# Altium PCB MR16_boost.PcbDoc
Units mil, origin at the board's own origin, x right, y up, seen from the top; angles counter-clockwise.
Board outline 800 x 860 mil, 2 copper layers (Top Layer, Bottom Layer), stack 62 mil thick; 24 components, 14 nets, 60 pads, 8 vias.
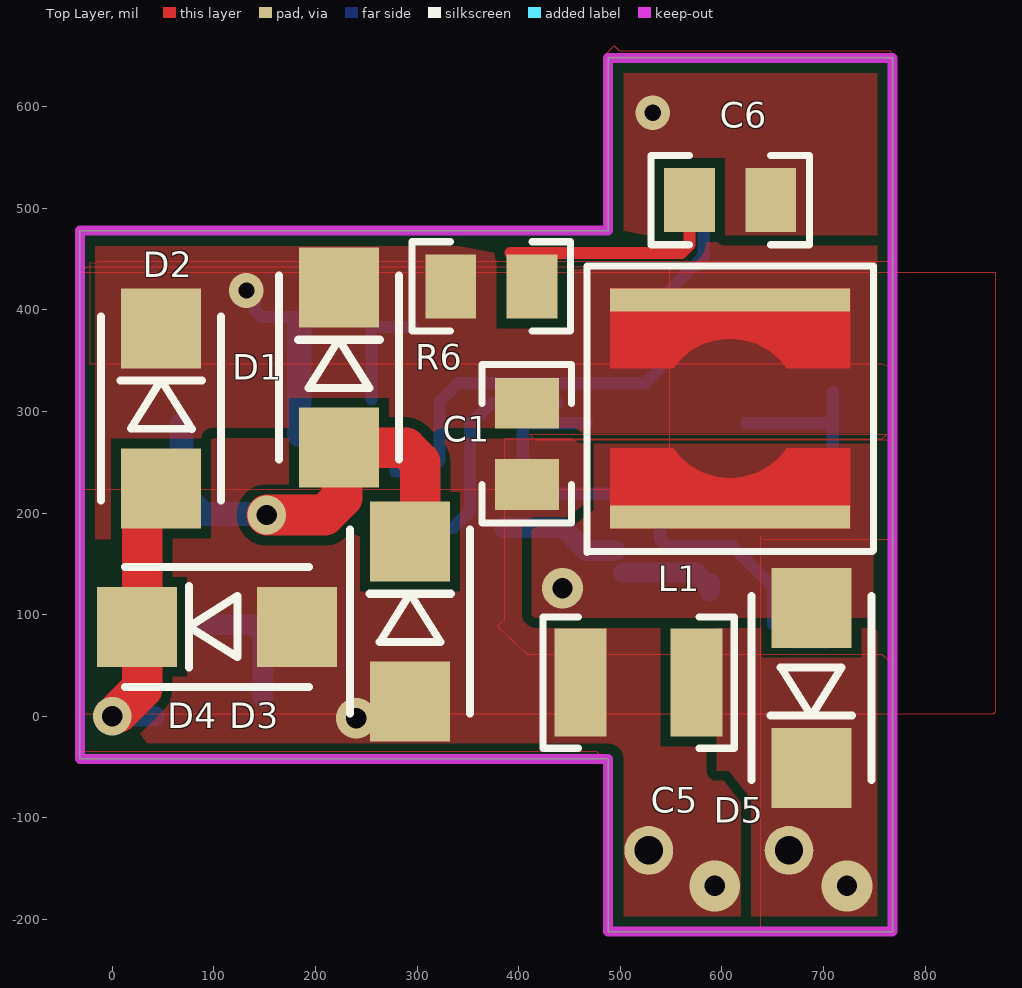
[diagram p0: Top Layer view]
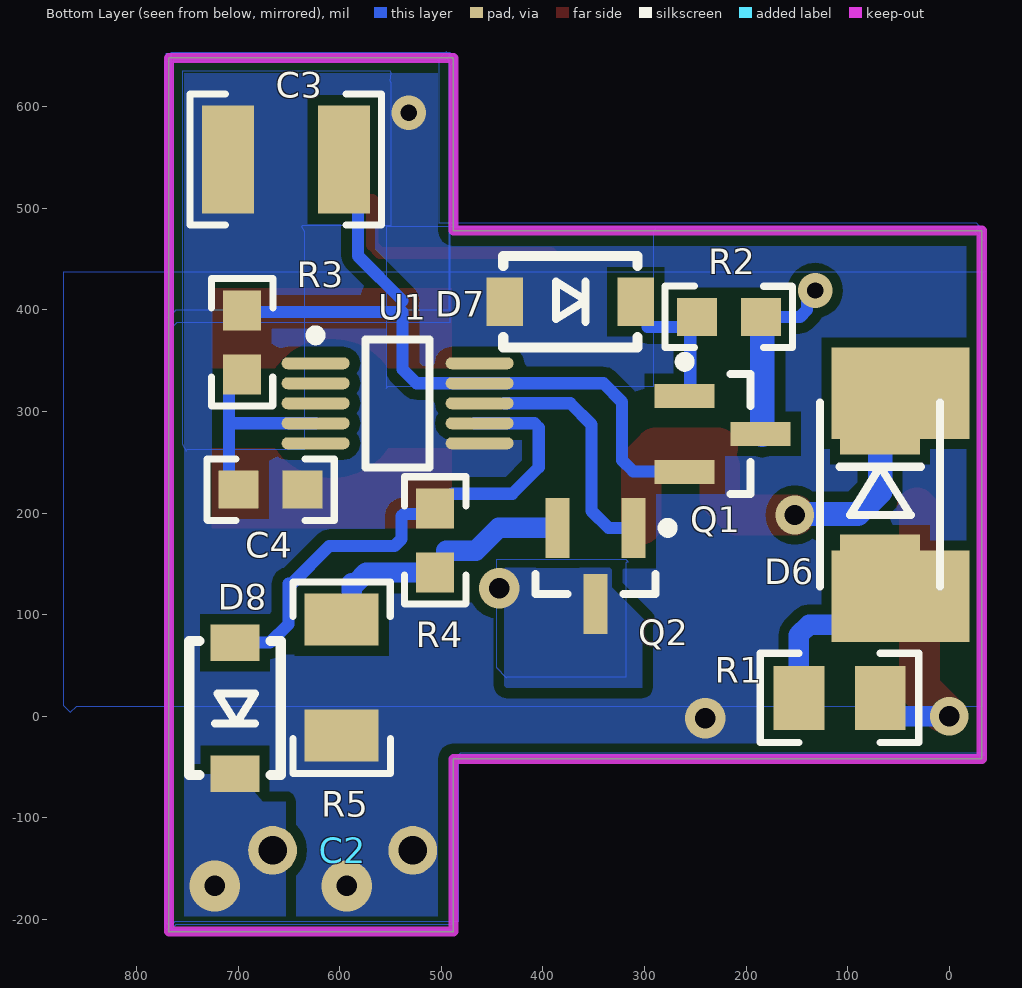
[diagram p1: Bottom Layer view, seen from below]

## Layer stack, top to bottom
Top Layer: signal copper 2
Dielectric: core 58, FR-4, Dk 4.8
Bottom Layer: signal copper 2

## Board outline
-32,-42 488,-42 488,-212 768,-212 768,648 488,648 488,478 -32,478

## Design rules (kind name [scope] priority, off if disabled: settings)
AssemblyTestPointUsage [All] p1: valid=2
Clearance [All] p1: gap=7
ComponentClearance ComponentClearance_ScrewToNut [(HasFootprint('NY PMS 440 0025 PH')) vs (HasFootprint('Keystone_1902C'))] p1: gap=5 collisioncheckmode=3 verticalgap=10 showdistances=FALSE
ComponentClearance ComponentClearance_MountingHoles [InComponentClass('Mounting Holes')] p2: gap=250 collisioncheckmode=3 verticalgap=100000 showdistances=FALSE
ComponentClearance ComponentClearance_SmallPassives [HasFootprint('0201*') or HasFootprint('0402*') or HasFootprint('0508') or HasFootprint('0603*') or HasFootprint('0612') or HasFootprint('0805*') or HasFootprint('0815*') or HasFootprint('0830*') or HasFootprint('1206*') or HasFootprint('1210*') or HasFootprint('1808*') or HasFootprint('1812*') or HasFootprint('1825*') or HasFootprint('2010*') or HasFootprint('2220*') or HasFootprint('2225*') or HasFootprint('2512*') or HasFootprint('2728*') or HasFootprint('3518*') vs HasFootprint('0201*') or HasFootprint('0402*') or HasFootprint('0508') or HasFootprint('0603*') or HasFootprint('0612') or HasFootprint('0805*') or HasFootprint('0815*') or HasFootprint('0830*') or HasFootprint('1206*') or HasFootprint('1210*') or HasFootprint('1808*') or HasFootprint('1812*') or HasFootprint('1825*') or HasFootprint('2010*') or HasFootprint('2220*') or HasFootprint('2225*') or HasFootprint('2512*') or HasFootprint('2728*') or HasFootprint('3518*')] p3: gap=20 collisioncheckmode=3 verticalgap=10 showdistances=FALSE
ComponentClearance ComponentClearance_THtoSMT [IsThruComponent vs IsSMTComponent] p4 off: gap=100 collisioncheckmode=3 verticalgap=100000 showdistances=FALSE
ComponentClearance ComponentClearance_THtoTH [IsThruComponent vs IsThruComponent] p5: gap=118.11 collisioncheckmode=3 verticalgap=100000 showdistances=FALSE
ComponentClearance [All] p6: gap=40 collisioncheckmode=3 verticalgap=10 showdistances=FALSE
DiffPairsRouting [All] p1: maxlimit=100 minlimit=10 mostfreqgap=10 maxuncoupledlength=1000
FabricationTestPointUsage TestPointUsage [All] p1: valid=2 allowmultiple=FALSE
FabricationTestpoint Testpoint [All] p1: side=3 testpointundercomponent=TRUE minsize=40 maxsize=100 preferedsize=60 minholesize=0 maxholesize=40 preferedholesize=32 testpointgrid=1 allowsidetop=TRUE allowsidebottom=TRUE usegrid=TRUE gridtolerance=0.01
FanoutControl Fanout_LCC [IsLCC] p1: bgadir=Out bgaviamode=Centered fanoutstyle=Auto fanoutdirection=Alternating viagrid=1 // Fanout_LCC (Default Rule)
FanoutControl Fanout_BGA [IsBGA] p2: bgadir=Out bgaviamode=Centered fanoutstyle=Auto fanoutdirection=Alternating viagrid=1 // Fanout_BGA (Default Rule)
FanoutControl Fanout_Default [All] p4: bgadir=Out bgaviamode=Centered fanoutstyle=Auto fanoutdirection=Alternating viagrid=1 // Fanout_Default (Default Rule)
FanoutControl Fanout_Small [(CompPinCount < 5)] p5: bgadir=Out bgaviamode=Centered fanoutstyle=Auto fanoutdirection=OutThenIn viagrid=1 // Fanout_Small (Default Rule)
HoleSize [All] p1: absolutevalues=TRUE maxlimit=251 minlimit=8 maxpercent=80.000 minpercent=20.000
MinimumAnnularRing [All] p1: minimumring=9
MinimumSolderMaskSliver [All] p1: minsoldermaskwidth=1
PlaneConnect [All] p1: planeconnectstyle=Direct reliefexpansion=20 reliefentries=4 reliefconductorwidth=10 reliefairgap=10
PolygonConnect [All] p1: connectstyle=Direct reliefconductorwidth=10 reliefentries=4 polygonreliefangle="90 Angle"
RoutingVias [All] p1: holewidth=25 width=40 viastyle="Through Hole" minholewidth=16 minwidth=30 maxholewidth=28 maxwidth=50
SilkToSilkClearance [All] p1: silktosilkclearance=2
SilkscreenOverComponentPads [All] p1: minsilkscreentomaskgap=2
SolderMaskExpansion [All] p1: expansion=3
Width [All] p1: maxlimit=100 minlimit=8 preferedwidth=12 minimp=50.000000 maximp=50.000000 favimp=50.000000
14 further rules are at their usual default settings.

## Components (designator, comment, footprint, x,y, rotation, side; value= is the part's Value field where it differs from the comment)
C1 "GRM216R61E105KA12D" 0805_HV 408,268 r270 top
C2 "ECA-1VHG221" PANASONIC_ECA_8X11.5MM 597,-132 r180 bottom
C3 "GRM32ER61E226KE15L" 1210 653,548 r0 bottom
C4 "06031C331JAT2A" 0603 668,223 r180 bottom
C5 "GRM32ER71H475KA88L" 1210 518,33 r180 top
C6 "GRM21BR61E475KA12L" 0805_HV 608,508 r0 top
D1 "B330A-13-F" SMA 223,343 r90 top
D2 "B330A-13-F" SMA 48,303 r90 top
D3 "B330A-13-F" SMA 293,93 r90 top
D4 "B330A-13-F" SMA 103,88 r180 top
D5 "B330A-13-F" SMA 688,28 r270 top
D6 "SMAJ24CA-13-F" SMA 68,218 r270 bottom
D7 "CMHZ4698" SOD-123 373,408 r0 bottom
D8 "CMHZ4714" SOD-123 703,8 r90 bottom
L1 "MSS6132-333MLB" MSS6132 608,303 r270 top
Q1 "BC848CLT1G" SOT-23 223,278 r180 bottom
Q2 "2N7002ET1G" SOT-23 348,148 r270 bottom
R1 "ERJ-6RSJR10V" 0805_HV 108,18 r180 bottom
R2 "CRCW06031K00FKEA" 0603 217,393 r180 bottom
R3 "CRCW060312K4FKEA" 0603 696,368 r270 bottom
R4 "CRCW06031K00FKEA" 0603 506,173 r90 bottom
R5 "CSR 1/2 1 1 I" 1206 598,38 r90 bottom
R6 "RC0805JR-074R7L" 0805_HV 373,423 r180 top
U1 "LM3444MM" MUB10A_N 543,308 r180 bottom

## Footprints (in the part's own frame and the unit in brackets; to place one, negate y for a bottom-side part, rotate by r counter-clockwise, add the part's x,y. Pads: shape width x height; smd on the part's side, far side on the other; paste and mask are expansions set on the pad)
0603 [mm] "0603 from SM-752 data"
  rect 1x0.95 smd: 1(-0.8,0) 2(0.8,0)
  silkscreen extent -1.59,-0.77 1.59,0.77, body extent -0.87,-0.47 0.87,0.47, height 0.85
0805_HV [mil] "0805 with 30mil clearance between pads"
  rect 50x63 smd: 1(-40,0) 2(40,0)
  silkscreen extent -78,-44 78,44, body extent -43,-29 43,29, height 43
1206 [mm] "1206 from SM-752 data"
  rect 1.3x1.85 smd: 1(-1.45,0) 2(1.45,0)
  silkscreen extent -2.39,-1.22 2.39,1.22, body extent -1.7,-0.9 1.7,0.9, height 1.35
1210 [mm] "1210 from SM-752 data"
  rect 1.3x2.7 smd: 1(-1.45,0) 2(1.45,0)
  silkscreen extent -2.39,-1.64 2.39,1.64, body extent -1.7,-1.35 1.7,1.35, height 1.35
MSS6132 [mm] "Coilcraft recommended land pattern Document 641-2 Revised 01/03/11"
  rect 0.575x6 smd: 1(-2.712,0) 2(2.712,0)
  Top Layer region: -1,-3 -1,-1.416 -1.003,-1.42 -1.232,-1.232 -1.449,-0.968 -1.61,-0.667 -1.709,-0.34 -1.742,0 -1.709,0.34 -1.61,0.667 -1.449,0.968 -1.232,1.232 -1.002,1.42 -1,1.417 -1,1.417 -1,1.425 -1,1.425 -1,3 -3,3 -3,-3
  Top Layer region: 1,-3 1,-1.416 1.003,-1.42 1.232,-1.232 1.449,-0.968 1.61,-0.667 1.709,-0.34 1.742,0 1.709,0.34 1.61,0.667 1.449,0.968 1.232,1.232 1.002,1.42 1,1.417 1,1.417 1,1.425 1,1.425 1,3 3,3 3,-3
  silkscreen extent -3.56,-3.58 3.61,3.58, body extent -3,-3 3,3, height 3.22
MUB10A_N [mm] "TSSOP, 10-Leads, Body 3x3mm, Pitch 0.5mm, IPC Medium Density"
  oval 1.7x0.3 smd: 1(-2.05,1) 2(-2.05,0.5) 3(-2.05,0) 4(-2.05,-0.5) 5(-2.05,-1) 6(2.05,-1) 7(2.05,-0.5) 8(2.05,0) 9(2.05,0.5) 10(2.05,1)
  silkscreen extent -2.17,-1.6 0.8,1.82, body extent -1.6,-1.6 1.6,1.6, height 1.09
PANASONIC_ECA_8X11.5MM [mil]
  round 48 hole 28: 1(-69,0) 2(69,0)
  body extent -157,-12 158,583, height 397
SMA [mm] "Molded Diode, 2-Leads, Body 4.3x2.6mm, IPC Medium Density, based on OnSemi component dimensions and land pattern"
  rect 2x2 smd: 1(-2,0) 2(2,0)
  silkscreen extent -2.3,-1.5 2.3,1.5, body extent -2.29,-1.46 2.28,1.46, height 2.27
SOD-123 [mm] "On Semi recommended land pattern"
  rect 0.915x1.22 smd: 1(-1.637,0) 2(1.637,0)
  silkscreen extent -1.68,-1.14 1.68,1.14, body extent -1.42,-0.9 1.42,0.9, height 1.35
SOT-23 [mm] "SOT23, 3-Leads, Body 2.9x1.3mm, Pitch 0.95mm, Lead Span 2.5mm, IPC Medium Density"
  rect 1.5x0.6 smd: 1(-0.95,0.95) 2(-0.95,-0.95) 3(0.95,0)
  silkscreen extent -1.07,-1.5 0.7,1.92, body extent -1.16,-1.45 1.21,1.45, height 1

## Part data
C1: "CAP, CERM, 1uF, 25V, +/-10%, X5R, 0805"
C2: library part Capacitor_Polarized, "CAP, AL, 220µF, 35V, +/-20%, TH bent"
C3: "CAP, CERM, 22uF, 25V, +/-10%, X5R, 1210"
C4: "CAP, CERM, 330pF, 100V, +/-5%, X7R, 0603"
C5: "CAP, CERM, 4.7uF, 50V, +/-10%, X7R, 1210"
C6: "CAP, CERM, 4.7uF, 25V, +/-10%, X5R, 0805"
D1 D2 D3 D4 D5: "Diode, Schottky, 30V, 3A, SMA"
D6: library part TVS_Diode, "TVS Diode, 400W, 24V, xx%, SMA"
D7: "Diode, Zener, 11V, 500mW, SOD-123"
D8: "Diode, Zener, 33V, 500mW, SOD-123"
L1: "Inductor, Shielded Drum Core, Ferrite, 33uH, 1.1A, 0.31 ohm, SMD"
Q1: library part "BC848CLT1G, ON Semiconductor", "Transistor, NPN, 30V, 0.1A, SOT-23"
Q2: "MOSFET, N-CH, 60V, 0.26A, SOT-23"
R1: "RES, 0.1 ohm, 5%, 0.125W, 0805"
R2 R4: "RES, 1.00k ohm, 1%, 0.1W, 0603"
R3: "RES, 12.4k ohm, 1%, 0.1W, 0603"
R5: "RES, 1.00 ohm, 1%, 0.5W, 1206"
R6: "RES, 4.7 ohm, 5%, 0.125W, 0805"
U1: library part LM3445MM/NOPB, "Triac Dimmable Offline LED Driver, 10-pin MSOP, Pb-Free"

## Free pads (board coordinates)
  rect 136x90 smd far side: 0(48,118) 0(48,318)

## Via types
v1: diameter 40, hole 20, Top Layer to Bottom Layer, 2 vias
v2: diameter 50, hole 20, Top Layer to Bottom Layer, 2 vias
v3: diameter 38, hole 20, Top Layer to Bottom Layer, 2 vias
v4: diameter 34, hole 16, Top Layer to Bottom Layer, 2 vias

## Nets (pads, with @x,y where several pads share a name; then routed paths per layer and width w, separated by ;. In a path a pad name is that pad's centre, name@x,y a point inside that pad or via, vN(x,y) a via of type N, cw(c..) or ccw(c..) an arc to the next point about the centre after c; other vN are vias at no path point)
GND: C1.2 C2.2 C3.2 C4.2 C5.2 C6.2 D3.1 D4.1 D7.2 R5.1 U1.6
  other v1: 240,-2
  other v2: 593,-167
  other v4: 532,594
NetC1_1: C1.1 D1.2 D2.2 L1.1 Q1.3 R2.2 R6.2 | length 161
  Bottom Layer w12: v4@140,407 140,400 147,393 R2.2
  Bottom Layer w24: Q1.3@184,277 R2.2@184,382.6
  other v4: 132,419
NetC2_1: C2.1 C5.1 D5.2 D8.1
  other v2: 723,-167
NetC3_1: C3.1 Q1.2 R3.1 U1.9 | length 665.7
  Bottom Layer w12: Q1.2@279,241 311,241 322,252 322,309.37 340.31,327.69 524.31,327.69 538,341.37 538,398 694.5,398 R3.1 ; 538,409 582,453 582,500 C3.1@587,505
NetC4_1: C4.1 R3.2 U1.4 | length 166
  Bottom Layer w12: U1.4 705.68,288.32 ; C4.1@709,235 R3.2@709,319
NetC6_1: C6.1 R6.1 | length 223.3
  Top Layer w12: 392,456 560,456 568,464 C6.1
NetD1_1: D1.1 D3.2 D6.1 pad.0@48,318 | length 405.8
  Top Layer w40: v3(152,198) 209,198 226,215 D1.1@226,246 ; D1.1@228,264.26 288.74,264.26 303,250 D3.2@303,189
  Bottom Layer w24: D6.1@68,286.74 68,221 90,199 v3@145,199
NetD2_1: D2.1 D4.2 R1.2 | length 253.8
  Top Layer w40: v3@6,4 29.26,27.26 29.26,88 29.26,202.26 D2.1@32,205
  Bottom Layer w20: v3(0,0) 42,0
NetD5_1: D5.1 L1.2 Q2.3
  other v1: 443,126
NetD6_2: D6.2 pad.0@48,118 R1.1 | length 122.1
  Bottom Layer w20: pad.0@92,90 138,90 148,80 R1.1
NetD7_1: D7.1 Q1.1 R2.1 | length 119.2
  Bottom Layer w12: Q1.1@255,312 R2.1@255,389.2 ; R2.1@255,383 297,383
NetD8_2: D8.2 R4.2 U1.7 | length 472
  Bottom Layer w12: U1.7@467.29,288.32 408.32,288.32 404,284 404,245 430,219 R4.2@489,219 ; R4.2@520,199 537,199 539,197 539,174.5 546,167.5 610.22,167.5 647,130.72 650.42,130.72 650.42,90.58 668.53,72.47 D8.2
NetQ2_1: Q2.1 U1.8 | length 228
  Bottom Layer w12: Q2.1 335.4,185.4 352,202 352,287 373,308 U1.8@438,308
NetQ2_2: Q2.2 R4.1 R5.2 | length 216.2
  Bottom Layer w20: Q2.2 443.6,185.4 466,163 495,163 ; R4.1@503,141.5 573.73,141.5 584.23,131 588,131 588,123
pads on no net: U1.1 U1.2 U1.3 U1.5 U1.10

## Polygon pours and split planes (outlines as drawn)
GND on Bottom Layer "Bottom Layer-No Net 8" (solid, shelved, pour order 1016): -30,482 -27,485 502,485 502,647 495,654 505,644 772,644 772,-208 770,-210 762,-202 483,-202 483,-40 481,-38 -35,-38 -35,467 -25,477
NetD5_1 on Bottom Layer "Bottom Layer-No Net 7" (solid, shelved, pour order 1015): 316,152 318,154 446,154 446,48 436,38 435,39 318,39 318,151 317,152
GND on Top Layer "Top Layer-No Net 7" (solid, shelved, pour order 1014): -29,482 -24,477 487,477 487,649 488,650 765,650 765,-209 766,-210 489,-210 489,-52 485,-48 475,-38 -35,-38 -35,481 -34,482
NetC1_1 on Top Layer "Top Layer-No Net 6" (solid, shelved, pour order 1010): -18.05,446 -14.11,448 770,448 770,347.33 763.42,344 758.16,346.67 -22,346.67 -22,446.67
NetD5_1 on Top Layer "Top Layer-No Net 5" (solid, shelved, pour order 1005): 411,277 416,272.33 770,272.33 770,52.87 768,51 758,60.34 410,60.34 409,60.34 379,88.36 386,94.89 386,273.26 758,273.26 762,277
no net on Top Layer "Top Layer-No Net 4" (solid, shelved, pour order 1001): 640,175 641,174 770,174 770,-211 768,-213 638,-213 638,177
GND on Top Layer "Top Layer-No Net 3" (solid, shelved, pour order 1013): -25,479 -23,481 486,481 486,646 488,648 489,649 767,649 767,-208 769,-210 767,-208 487,-208 487,-45 477,-35 -33,-35 -33,481
GND on Bottom Layer "Bottom Layer-No Net 6" (solid, shelved, pour order 1009): -34,482 485,482 485,649 487,651 488,652 766,652 766,-210 765,-211 764,-210 488,-210 488,-43 486,-41 481,-36 -35,-36 -35,480 -34,481
NetC1_1 on Bottom Layer "Bottom Layer-No Net 5" (solid, shelved, pour order 1004): 290,482 554,482 554,323 552,325 291,325 291,478 289,480
no net on Bottom Layer "Bottom Layer-No Net 4" (solid, shelved, pour order 1008): 490,652 491,653 766,653 766,388 763,385 760,388 491,388 491,640 487,644
GND on Top Layer "Top Layer-No Net 1" (solid, shelved, pour order 1007): -30,438 -29,437 869,437 869,4 867,2 -33,2 -33,435 -32,436
NetC1_1 on Top Layer "Top Layer-No Net" (solid, shelved, pour order 1003): -27,440.55 -25,442.27 548,442.27 548,225.59 545,223 -33,223 -33,441.41 -30,444
GND on Bottom Layer "Bottom Layer-No Net" (solid, shelved, pour order 1012): -36,438 -35,437 872,437 872,11 865,4 859,10 -33,10 -33,437 -34,438
no net on Bottom Layer "Bottom Layer-No Net 1" (solid, shelved, pour order 1000): 549,633.35 549.96,635 755,635 755,267.59 751.17,261 750.21,262.65 634.27,262.65 634.27,476.83 637.15,481.78 636.19,483.42 549,483.42 549,623.47 549.96,625.11
GND on Bottom Layer "Bottom Layer-No Net 3" (solid, shelved, pour order 1006): -34,477 -30,481 487,481 487,646 493,652 771,652 771,-203 765,-209 761,-205 489,-205 489,-42 487,-40 485,-42 -30,-42 -30,481 -28,483
no net on Bottom Layer "Bottom Layer-No Net 2" (solid, shelved, pour order 1002): 491,651 496,646 764,646 764,397 769,392 761,400 492,400 492,645 494,647
GND on Top Layer "Top Layer-No Net 2" (solid, shelved, pour order 1011): -33,480 485,480 485,651 494,660 499,655 766,655 766,-210 767,-211 766,-212 485,-212 485,-45 480,-40 -33,-40 -33,476 -32,477
GND on Top Layer "Top Layer-No Net 11" (solid, pour order 1002): -28,485 487,485 485,487 485,649 767,649 771,645 763,637 763,-211 486,-211 481,-206 479,-204 479,-45 -19,-45 -29,-35 -32,-32 -32,480
NetD5_1 on Top Layer "Top Layer-No Net 9" (solid, pour order 1001): 416,185.96 447,185.96 452,185.96 471,200.91 474,203.28 474,281.21 749,281.21 750,282 749,281.21 749,97 416,97 414,98.57 413,99.36 413,186.74
NetC1_1 on Top Layer "Top Layer-No Net 8" (solid, pour order 1000): -30,487.86 -27,491 473,491 473,482.64 502,452.32 530,481.59 762,481.59 762,170.05 763,169 758,174.23 -30,174.23 -30,484.73 -33,487.86
NetC2_1 on Top Layer "Top Layer-No Net 10" (solid, pour order 1002): 594.13,104.03 595.7,106 756.22,106 756.22,-209.02 757,-210 751.52,-203.11 628.58,-203.11 628.58,-81.04 621.54,-72.18 606.66,-53.48 594.92,-53.48 594.92,99.11 591,104.03
NetC2_1 on Bottom Layer "Bottom Layer-No Net 9" (solid, pour order 1004): 653.85,-206 653,-205 653,-84 675.92,-84 698.84,-57 766.76,-57 766.76,-210 771,-215 763.36,-206 653,-206
NetD5_1 on Bottom Layer "Bottom Layer-No Net 10" (solid, pour order 1005): 334,146 437,146 438,145 438,60 438,28 437,27 436,28 302,28 302,93 300,95 332,127 332,144
GND on Bottom Layer "Bottom Layer-No Net 11" (solid, pour order 1006): -38,475 485,475 491,481 489,483 489,652 769,652 771,654 765,648 765,-207 489,-207 485,-211 485,-42 -24,-42 -32,-34 -34,-32 -34,479

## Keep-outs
Keep-Out Layer:
  the board outline again, w10
  text ".Layer_Name" at -815,-2370.49 h60
  text "880" at 1725.5,-2370.49 h60

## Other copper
Top Layer:
  text ".Layer_Name" at -815,-2370.49 h60
  text "880" at 1725.5,-2370.49 h60
Bottom Layer:
  text ".Layer_Name" at -815,-2370.49 h60
  text "880" at 1725.5,-2370.49 h60

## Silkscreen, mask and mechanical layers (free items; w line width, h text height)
Top Overlay:
  text ".Layer_Name" at -815,-2370.49 h60
  text "880" at 1725.5,-2370.49 h60
Bottom Overlay:
  text ".Layer_Name" at -815,-2370.49 h60
  text "880" at 1725.5,-2370.49 h60
Top Paste:
  text ".Layer_Name" at -815,-2370.49 h60
  text "881" at 1725.5,-2370.49 h60
Bottom Paste:
  text ".Layer_Name" at -815,-2370.49 h60
  text "881" at 1725.5,-2370.49 h60
Top Solder:
  text ".Layer_Name" at -815,-2370.49 h60
  text ".Layer_Name" at -815,-2370.49 h60
  text "880" at 1725.5,-2370.49 h60
Bottom Solder:
  text ".Layer_Name" at -815,-2370.49 h60
  text "880" at 1725.5,-2370.49 h60
Drill Guide:
  text ".Layer_Name" at -815,-2370.49 h60
  text "880" at 1725.5,-2370.49 h60
M1 Board Outline:
  the board outline again, w10
  text ".Layer_Name" at -815,-2370.49 h60
  text "880" at 1725.5,-2370.49 h60
M2 Board Dimensions:
  rectangle: -1392.5,-1797.5 -1267.5,-1672.5
  rectangle: -1267.5,-1922.5 -892.5,-1797.5
  lines w7: -1392.5,-1797.5 -392.5,-1797.5 ; -1267.5,-1922.5 -1267.5,-1672.5 ; -1142.5,-1922.5 -1142.5,-1672.5 ; -892.5,-1922.5 -892.5,-1672.5 ; -642.5,-1922.5 -642.5,-1672.5 ; -1392.5,-1922.5 -392.5,-1922.5 -392.5,-1672.5 -1392.5,-1672.5 -1392.5,-1922.5
  lines w10: -1392.5,-1987.5 -1392.5,-1967.5 ; -1332.5,-1997.5 -1392.5,-1977.5 ; -1332.5,-1957.5 -1392.5,-1977.5 ; -1168.42,-1977.5 -1392.5,-1977.5 ; -616.58,-1977.5 -392.5,-1977.5 ; -452.5,-1997.5 -392.5,-1977.5 ; -452.5,-1957.5 -392.5,-1977.5 ; -392.5,-1987.5 -392.5,-1967.5
  text "1000 (mil)" at -1158.42,-2013.49 h60
  text ".Layer_Name" at -815,-2370.49 h60
  text "880" at 1725.5,-2370.49 h60
M3 3D STEP Top:
  text ".Layer_Name" at -815,-2370.49 h60
  text "880" at 1725.5,-2370.49 h60
M4 3D STEP Bottom:
  text ".Layer_Name" at -815,-2370.49 h60
  text "880" at 1725.5,-2370.49 h60
M5 Assembly Top:
  lines w7: -1684,-2442.17 4916,-2442.17 ; -1684,-2238.83 4918,-2238.83 ; -1684,-2035.5 -1684,-2645.5 2321,-2645.5 4918,-2645.5 4918,-2035.5 -1683.5,-2035.5 -1683.5,-2645.5 -108,-2645.5 ; 781,-2441 781,-2035.5 ; 2534,-2645 2534,-2445 ; 3510,-2442 3510,-2239.17
  text "COMPONENTS MARKED 'DNP' SHOULD NOT BE POPULATED, AND MAY NOT BE IN BILL OF MATERIALS" at -238.5,-1830.5 h60
  text "ASSEMBLY VARIANT:" at -239,-1946 h60
  text ".VariantName" at 797,-1946 h60
  text "PCB VIEWED FROM TOP SIDE" at -1620.5,-2167.67 h60
  text "PROJECT NAME =" at 856,-2167.67 h60
  text ".PRJ_Title" at 1725.5,-2167.67 h60
  text "-" at 2270,-2368.49 h60
  text ".PCB_SilkRev" at 2527,-2368.49 h60
  text "NATIONAL SEMICONDUCTOR" at 3581,-2368.49 h60
  text "LAYER NAME =" at -1620.5,-2370.49 h60
  text "ARTWORK #    =" at 856,-2370.49 h60
  text ".prj_BasePN" at 1901.5,-2370.49 h60
  text ".PCB_CopperRev" at 2337.5,-2370.49 h60
  text "PLOT NAME =" at -1620.5,-2576.34 h60
  text ".plot_File_Name" at -815,-2576.34 h60
  text "GENERATED    :" at 2606,-2576.34 h60
  text ".Print_Date" at 3475.5,-2576.34 h60
  text ".Print_Time" at 4204.5,-2576.34 h60
M6 Assembly Bottom:
  lines w7: -1684,-2238.83 4918,-2238.83 ; -1682,-2442.17 4918,-2442.17 ; -276,-2442.5 -276,-2239.17 ; 742,-2645 742,-2443 ; 2453,-2441 2453,-2035.5 ; 3342,-2645.5 4917.5,-2645.5 4917.5,-2035.5 -1684,-2035.5 -1684,-2645.5 913,-2645.5 4918,-2645.5 4918,-2035.5
  text "COMPONENTS MARKED 'DNP' SHOULD NOT BE POPULATED, AND MAY NOT BE IN BILL OF MATERIALS" at 4710,-1830 h60
  text ".VariantName" at 3666,-1946 h60
  text "ASSEMBLY VARIANT:" at 4705,-1946 h60
  text ".PRJ_Title" at 1508.5,-2167.67 h60
  text "PROJECT NAME =" at 2378,-2167.67 h60
  text "PCB VIEWED FROM BOTTOM SIDE" at 4854.5,-2167.67 h60
  text "-" at 923,-2368.49 h60
  text "NATIONAL SEMICONDUCTOR" at -347,-2370.49 h60
  text ".PCB_SilkRev" at 692,-2370.49 h60
  text ".PCB_CopperRev" at 893,-2370.49 h60
  text ".prj_BasePN" at 1332.5,-2370.49 h60
  text "880" at 1516,-2370.49 h60
  text "ARTWORK #    =" at 2378,-2370.49 h60
  text "LAYER NAME =" at 4854.5,-2370.49 h60
  text ".Print_Time" at -970.5,-2576.34 h60
  text ".Print_Date" at -241.5,-2576.34 h60
  text "GENERATED    :" at 628,-2576.34 h60
  text ".plot_File_Name" at 4049,-2576.34 h60
  text "PLOT NAME =" at 4854.5,-2576.34 h60
M9 Title Sheet:
  drawing of 64 lines, arcs and shapes, not listed
  text "1" at -652.16,6524.5 h70
  text "2" at 1843.5,6524.5 h70
  text "3" at 4332.84,6524.5 h70
  text "4" at 6839.51,6524.5 h70
  text "5" at 9338.5,6524.5 h70
  text "6" at 11843.5,6524.5 h70
  text "A" at -1808.5,5381.5 h70
  text "A" at 12991.5,5381.5 h70
  text "B" at -1808.5,3001.5 h70
  text "B" at 12991.5,3001.5 h70
  text "C" at -1808.5,626.5 h70
  text "C" at 12991.5,626.5 h70
  text "PROJECT TITLE:" at 9951.5,-1234.5 h45
  text ".PRJ_Title" at 10001.5,-1367.83 h70
  text "FILE NAME:" at 9951.5,-1535.5 h45
  text ".PCB_File_Name_No_Path" at 10001.5,-1655.5 h70
  text "D" at -1808.5,-1743.5 h70
  text "D" at 12991.5,-1743.5 h70
  text "FAB DRAWING NUMBER:" at 9951.5,-1825.5 h45
  text "551" at 10001.5,-1980.49 h70
  text ".PRJ_BasePN" at 10196.5,-1980.49 h70
  text "-" at 10605,-1980.49 h70
  text ".PCB_CopperRev" at 10678,-1980.49 h70
  text ".PCB_SilkRev" at 10903,-1980.49 h70
  text "National Semiconductor and/or its licensors do not warrant the accuracy or completeness of this specification" at 4982,-2117.34 h45
  text "DESIGNED FOR:" at 9951.5,-2135.5 h45
  text "or any information contained therein. National and/or its licensors do not warrant that this design will meet" at 4937.01,-2230 h45
  text ".PRJ_Customer" at 10001.5,-2275.5 h70
  text "the specifications, will be suitable for your application or fit for any particular purpose, or will operate in" at 4937.01,-2342.67 h45
  text ".Layer_Name" at -815,-2370.49 h60
  text ".Layer_Name" at -815,-2370.49 h60
  text "880" at 1725.5,-2370.49 h60
  text "880" at 1725.5,-2370.49 h60
  text "ALTIUM DESIGNER VERSION:" at 11496.5,-2435.5 h45
  text "an implementation. National and/or its licensors do not warrant that the design is production worthy. You should" at 4937.01,-2455.33 h45
  text ".print_Scale" at 10001.5,-2537.5 h70
  text "completely validate and test your design implementation to confirm the system functionality for your application." at 4982,-2568 h45
  text ".Application_BuildNumber" at 11546.5,-2568.83 h70
  text "1" at -652.16,-2775.5 h70
  text "2" at 1843.5,-2775.5 h70
  text "3" at 4332.84,-2775.5 h70
  text "4" at 6839.51,-2775.5 h70
  text "5" at 9338.5,-2775.5 h70
  text "6" at 11843.5,-2775.5 h70
M10 Fab Notes:
  text ".Layer_Name" at -815,-2370.49 h60
  text "880" at 1725.5,-2370.49 h60
M11 Gerber Information:
  lines w7: -1684,-2442.17 4916,-2442.17 ; -1684,-2238.83 4918,-2238.83 ; -1684,-2035.5 -1684,-2645.5 2321,-2645.5 4918,-2645.5 4918,-2035.5 -1683.5,-2035.5 -1683.5,-2645.5 -108,-2645.5 ; 781,-2441 781,-2035.5 ; 2534,-2645 2534,-2445 ; 3510,-2442 3510,-2239.17
  text "ALL ARTWORK VIEWED FROM TOP SIDE" at -1620.5,-2167.67 h60
  text "PROJECT NAME =" at 856,-2167.67 h60
  text ".PRJ_Title" at 1725.5,-2167.67 h60
  text "-" at 2270,-2368.49 h60
  text ".PCB_SilkRev" at 2527,-2368.49 h60
  text "NATIONAL SEMICONDUCTOR" at 3581,-2368.49 h60
  text "LAYER NAME =" at -1620.5,-2370.49 h60
  text "ARTWORK #    =" at 856,-2370.49 h60
  text ".prj_BasePN" at 1901.5,-2370.49 h60
  text ".PCB_CopperRev" at 2337.5,-2370.49 h60
  text "PLOT NAME =" at -1620.5,-2576.34 h60
  text ".plot_File_Name" at -815,-2576.34 h60
  text "GENERATED    :" at 2606,-2576.34 h60
  text ".Print_Date" at 3475.5,-2576.34 h60
  text ".Print_Time" at 4204.5,-2576.34 h60
M12 Stackup:
  text ".Layer_Name" at -815,-2370.49 h60
  text "880" at 1725.5,-2370.49 h60
M13 Component Bodies Top:
  text ".Layer_Name" at -815,-2370.49 h60
  text "880" at 1725.5,-2370.49 h60
M14 Component Bodies Bottom:
  text ".Layer_Name" at -815,-2370.49 h60
  text "880" at 1725.5,-2370.49 h60
M15 Courtyards Top:
  text ".Layer_Name" at -815,-2370.49 h60
  text "880" at 1725.5,-2370.49 h60
M16 Courtyards Bottom:
  text ".Layer_Name" at -815,-2370.49 h60
  text "880" at 1725.5,-2370.49 h60
Drill Drawing:
  text ".LEGEND" at 1121,154 h25
  text "Drill Drawing." at 1121,54 h25
  text ".Layer_Name" at -815,-2370.49 h60
  text "880" at 1725.5,-2370.49 h60

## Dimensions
778,-213 to 1055,647 on M2 Board Dimensions
-32,-61 to 488,-42 on M2 Board Dimensions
